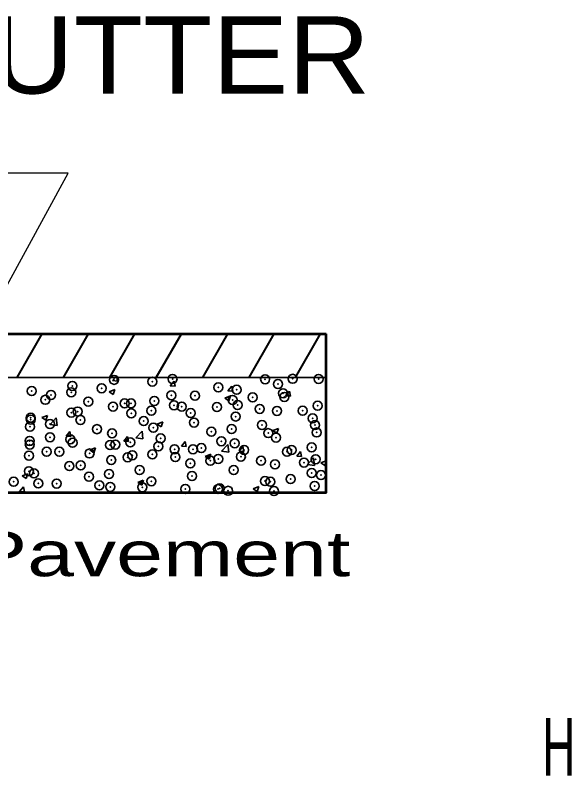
# Model space of a CAD drawing. Extents: x 14 to 49.3, y 28 to 50.
# Drawn here: x 28.309 to 30.04, y 36.954 to 39.319 of the extents above; entities that cross this region are included whole.
import ezdxf

# ---------------------------------------------------------------- set-up
doc = ezdxf.new("R2010")
doc.units = 0
doc.header["$LTSCALE"] = 0.056
doc.header["$PDMODE"] = 32
doc.header["$PDSIZE"] = 0.028
for name, color, linetype, lineweight in [('1', 7, 'Continuous', 35), ('3', 7, 'Continuous', 13), ('5', 7, 'Continuous', 35)]:
    doc.layers.add(name, color=color, linetype=linetype, lineweight=lineweight)

msp = doc.modelspace()

# ---------------------------------------------------------------- linework, layer by layer
at = {"layer": '1', "lineweight": 53}
for p in [(25.70917, 38.32767), (29.27625, 38.1925)]:
    msp.add_line(p, (29.27625, 38.32767), dxfattribs=at)
at = {"layer": '1', "lineweight": 40}
for p, q in [((28.31475, 38.1925), (28.39275, 38.32767)), ((28.45908, 38.1925), (28.53708, 38.32767)), ((28.60342, 38.1925), (28.68142, 38.32767)), ((28.74775, 38.1925), (28.82575, 38.32767)), ((28.89208, 38.1925), (28.97008, 38.32767)), ((29.03642, 38.1925), (29.11442, 38.32767)), ((29.18075, 38.1925), (29.25875, 38.32767)), ((28.69983, 37.8595), (28.70733, 37.87258))]:
    msp.add_line(p, q, dxfattribs=at)
at = {"layer": '1'}
for p, q in [((29.27625, 38.1925), (25.73192, 38.1925)), ((28.61183, 38.1825), (28.62025, 38.1925)), ((28.61183, 38.1825), (28.62675, 38.18125)), ((28.62675, 38.18117), (28.62467, 38.1925)), ((28.79117, 38.16683), (28.80317, 38.18117)), ((28.80608, 38.1655), (28.80325, 38.18117)), ((28.60158, 38.14817), (28.61908, 38.15483)), ((28.614, 38.13975), (28.61908, 38.15483)), ((28.79117, 38.16683), (28.80608, 38.1655)), ((28.79117, 38.16683), (28.80608, 38.1655)), ((28.9705, 38.15117), (28.9825, 38.1655)), ((28.98542, 38.14983), (28.9825, 38.1655)), ((28.60158, 38.14817), (28.614, 38.13975)), ((28.96083, 38.12808), (28.97833, 38.13483)), ((28.9705, 38.15117), (28.98542, 38.14983)), ((28.97325, 38.11967), (28.97833, 38.13483)), ((29.14975, 38.1355), (29.16183, 38.14983)), ((29.14975, 38.1355), (29.16475, 38.13417)), ((29.16475, 38.13417), (29.16183, 38.14983)), ((28.96083, 38.12808), (28.97325, 38.11975)), ((28.3915, 38.0675), (28.409, 38.07425)), ((28.3915, 38.0675), (28.40392, 38.05908)), ((28.40392, 38.05908), (28.409, 38.07417)), ((28.41725, 38.04617), (28.43675, 38.0665)), ((28.4395, 38.04275), (28.43675, 38.0665)), ((28.4395, 38.04275), (28.43675, 38.0665)), ((28.41725, 38.04617), (28.4395, 38.04275)), ((28.75075, 38.0475), (28.76825, 38.05417)), ((28.75075, 38.0475), (28.76325, 38.03908)), ((28.76325, 38.03908), (28.76833, 38.05417)), ((28.46725, 38.01017), (28.47925, 38.0245)), ((28.48217, 38.00883), (28.47925, 38.0245)), ((28.68408, 38.00483), (28.70358, 38.02508)), ((28.70633, 38.00133), (28.70358, 38.02508)), ((29.11008, 38.02742), (29.12758, 38.03417)), ((29.11008, 38.02742), (29.1225, 38.01908)), ((29.1225, 38.01908), (29.12758, 38.03417)), ((28.46725, 38.01017), (28.48217, 38.00883)), ((28.6465, 37.9945), (28.65858, 38.00883)), ((28.6465, 37.9945), (28.6615, 37.99317)), ((28.6615, 37.99317), (28.65858, 38.00883)), ((28.68408, 38.00483), (28.70633, 38.00133)), ((28.82583, 37.97875), (28.83792, 37.99317)), ((28.84083, 37.9775), (28.83792, 37.99317)), ((28.54075, 37.96683), (28.55825, 37.97358)), ((28.54075, 37.96683), (28.55317, 37.95842)), ((28.55317, 37.95842), (28.55825, 37.97358)), ((28.82583, 37.97875), (28.84075, 37.9775)), ((28.95092, 37.96342), (28.97033, 37.98375)), ((28.97317, 37.96), (28.97042, 37.98367)), ((29.00517, 37.96308), (29.01725, 37.9775)), ((29.02008, 37.96175), (29.01725, 37.97742)), ((28.9, 37.94683), (28.9175, 37.9535)), ((28.9, 37.94683), (28.91242, 37.93842)), ((28.91242, 37.93842), (28.9175, 37.9535)), ((28.95092, 37.96342), (28.97317, 37.96)), ((29.00517, 37.96308), (29.02008, 37.96183)), ((29.1845, 37.94742), (29.1965, 37.96175)), ((29.1845, 37.94742), (29.19942, 37.94608)), ((29.19942, 37.94608), (29.1965, 37.96175)), ((29.21775, 37.922), (29.23717, 37.94233)), ((29.23992, 37.91858), (29.23717, 37.94233)), ((29.21775, 37.922), (29.23992, 37.91858)), ((29.25925, 37.92683), (29.27625, 37.93333)), ((29.25925, 37.92683), (29.27175, 37.91842)), ((29.27175, 37.91842), (29.27625, 37.93192)), ((28.33067, 37.88617), (28.34817, 37.89292)), ((28.33067, 37.88617), (28.34308, 37.87783)), ((28.34308, 37.87783), (28.34817, 37.89292)), ((28.68992, 37.86617), (28.70742, 37.87292)), ((28.70242, 37.85775), (28.7075, 37.87292)), ((28.32258, 37.83783), (28.33467, 37.85217)), ((28.3375, 37.8365), (28.33467, 37.85217)), ((28.68992, 37.86617), (28.70242, 37.85783)), ((29.04925, 37.84617), (29.06675, 37.85292)), ((29.06167, 37.83775), (29.06675, 37.85283)), ((28.32258, 37.83783), (28.3375, 37.8365)), ((28.51267, 37.83492), (28.51392, 37.8365)), ((28.51425, 37.83492), (28.514, 37.8365)), ((29.04925, 37.84617), (29.06167, 37.83775))]:
    msp.add_line(p, q, dxfattribs=at)
at = {"layer": '1', "lineweight": 53}
msp.add_lwpolyline([(25.70917, 37.83492), (29.27625, 37.83492), (29.27625, 38.1925)], dxfattribs=at)
at = {"layer": '1'}
for p in [(28.79817, 38.18767), (29.17225, 38.18817), (29.25258, 38.18767), (28.48667, 38.16625), (28.6165, 38.185), (28.73558, 38.17942), (29.08642, 38.18658), (29.12633, 38.17167), (28.36042, 38.15025), (28.483, 38.14617), (28.57767, 38.15867), (28.94058, 38.16158), (28.99792, 38.15408), (29.14225, 38.14308), (28.4025, 38.12283), (28.42042, 38.138), (28.536, 38.11725), (28.74183, 38.11933), (28.79483, 38.13658), (28.86808, 38.13533), (28.985, 38.12233), (29.04758, 38.13058), (29.14633, 38.13167), (28.6135, 38.10175), (28.649, 38.1115), (28.66942, 38.11158), (28.80292, 38.10592), (28.82708, 38.10158), (28.93633, 38.10033), (29.0005, 38.10667), (29.06975, 38.09467), (29.24958, 38.1045), (28.48358, 38.083), (28.50325, 38.0865), (28.66983, 38.08083), (28.73242, 38.08908), (28.85475, 38.08167), (28.99492, 38.07092), (29.12325, 38.0885), (29.20325, 38.089), (28.35733, 38.067), (28.35742, 38.0615), (28.41725, 38.04758), (28.51192, 38.06008), (28.70892, 38.05667), (28.86508, 38.05217), (29.23433, 38.06525), (28.35467, 38.03933), (28.56308, 38.03158), (28.73875, 38.03617), (28.91925, 38.02375), (28.98183, 38.032), (29.0765, 38.04442), (29.24175, 38.04425), (28.41733, 38.00658), (28.48058, 37.99975), (28.61042, 38.0185), (28.76133, 38.00292), (29.096, 38.01917), (29.12025, 38.00525), (29.2465, 38.02125), (28.35383, 37.99508), (28.35433, 37.98375), (28.48725, 37.9895), (28.60408, 37.98225), (28.62075, 37.98383), (28.66667, 37.9905), (28.75417, 37.97817), (28.95017, 37.99417), (28.99183, 37.98767), (29.23117, 37.97483), (28.4065, 37.9615), (28.44617, 37.9615), (28.54, 37.95592), (28.73575, 37.95292), (28.80442, 37.96917), (28.862, 37.96892), (28.88767, 37.97258), (29.02108, 37.96692), (29.15458, 37.96125), (29.16858, 37.96658), (28.3515, 37.949), (28.60742, 37.93533), (28.65858, 37.94408), (28.67342, 37.95025), (28.80692, 37.94458), (28.916, 37.93333), (28.94033, 37.939), (29.01075, 37.94583), (29.07383, 37.93333), (29.20725, 37.92767), (29.2435, 37.938), (28.47758, 37.91658), (28.51283, 37.91908), (28.69558, 37.90433), (28.85342, 37.92517), (28.98883, 37.90442), (29.11717, 37.922), (28.35125, 37.90058), (28.367, 37.89408), (28.53825, 37.88367), (28.60092, 37.89192), (28.859, 37.88567), (29.2315, 37.89508), (29.26008, 37.88875), (28.30408, 37.868), (28.38042, 37.86283), (28.43758, 37.86242), (28.571, 37.85675), (28.73275, 37.86967), (29.08567, 37.87), (29.10283, 37.868), (29.16542, 37.87625), (28.60433, 37.85208), (28.70442, 37.85108), (28.83792, 37.8455), (28.93983, 37.845), (28.94492, 37.84725), (28.97133, 37.83983), (29.11417, 37.83883), (29.24042, 37.85483)]:
    msp.add_point(p, dxfattribs=at)
at = {"layer": '3', "lineweight": 25}
msp.add_lwpolyline([(28.08658, 38.1195), (28.4735, 38.82825), (28.14783, 38.82825)], dxfattribs=at)

# ---------------------------------------------------------------- texts
at = {"layer": '3'}
for s, height, width, p in [('CURB AND GUTTER', 0.24, 1.1, (26.01958, 39.07542)), ('Concrete Transition Pavement', 0.14, 1.4, (25.81142, 37.57425))]:
    msp.add_text(s, height=height, dxfattribs=dict(at, width=width)).set_placement(p)
at = {"layer": '5', "width": 0.6}
msp.add_text('H', height=0.18, dxfattribs=at).set_placement((29.94783, 36.95358))

doc.saveas('drawing.dxf')
